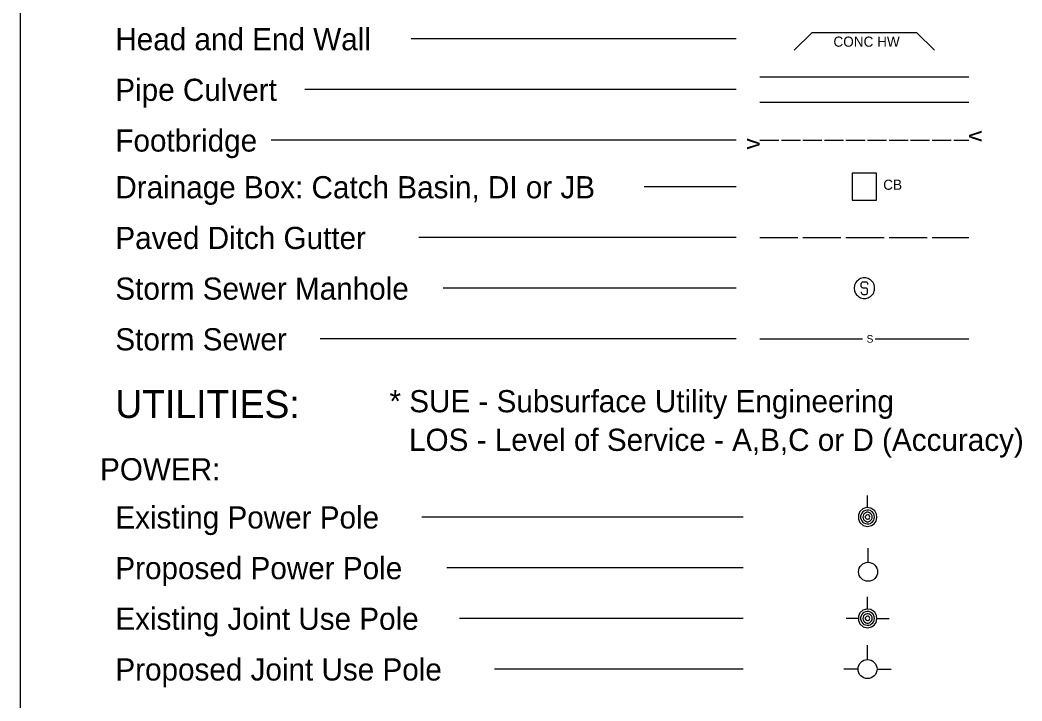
# Model space of a CAD drawing. Extents: x 811508 to 813252, y 647626 to 648754.
# Drawn here: x 812380 to 812789.1, y 648192.9 to 648471 of the extents above; entities that cross this region are included whole.
import ezdxf

# ---------------------------------------------------------------- set-up
doc = ezdxf.new("R2010")
doc.units = 0
doc.layers.add('Sheet_Symbology', color=7, linetype='Continuous')
doc.layers.add('z - Construction', color=7, linetype='Continuous')

msp = doc.modelspace()

# ---------------------------------------------------------------- linework, layer by layer
at = {"layer": 'Sheet_Symbology'}
for p, q in [((812672.47, 648463.4), (812539.68, 648463.4)), ((812696.12, 648458.66), (812703.44, 648465.99)), ((812703.44, 648465.99), (812746.13, 648465.99)), ((812746.13, 648465.99), (812753.46, 648458.66)), ((812682.1, 648447.87), (812767.48, 648447.87)), ((812672.47, 648442.7), (812496.33, 648442.7)), ((812682.1, 648437.53), (812767.48, 648437.53)), ((812672.47, 648422), (812482.58, 648422)), ((812682.1, 648422), (812689.86, 648422)), ((812690.89, 648422), (812698.66, 648422)), ((812699.69, 648422), (812707.45, 648422)), ((812708.49, 648422), (812716.25, 648422)), ((812717.28, 648422), (812725.05, 648422)), ((812726.08, 648422), (812733.84, 648422)), ((812734.88, 648422), (812742.64, 648422)), ((812743.68, 648422), (812751.44, 648422)), ((812752.47, 648422), (812760.24, 648422)), ((812761.27, 648422), (812767.48, 648422)), ((812672.47, 648402.92), (812634.91, 648402.92)), ((812672.47, 648382.22), (812542.91, 648382.22)), ((812682.1, 648382.22), (812697.62, 648382.22)), ((812699.69, 648382.22), (812715.22, 648382.22)), ((812717.28, 648382.22), (812732.81, 648382.22)), ((812734.88, 648382.22), (812750.4, 648382.22)), ((812752.47, 648382.22), (812767.48, 648382.22)), ((812672.47, 648361.52), (812552.75, 648361.52)), ((812723.54, 648362.26), (812723.54, 648363.37)), ((812724.28, 648364.11), (812725.39, 648364.11)), ((812725.39, 648361.55), (812724.28, 648361.55)), ((812726.1, 648363.37), (812726.1, 648363)), ((812726.1, 648359.7), (812726.1, 648360.85)), ((812723.54, 648360.07), (812723.54, 648359.7)), ((812724.28, 648359), (812725.39, 648359)), ((812672.47, 648340.82), (812502.53, 648340.82)), ((812682.1, 648340.82), (812724.04, 648340.82)), ((812729.21, 648340.82), (812767.48, 648340.82)), ((812726.08, 648271.88), (812726.08, 648276.85)), ((812675.36, 648268.06), (812544.05, 648268.06)), ((812726.3, 648249.55), (812726.3, 648255.37)), ((812675.36, 648247.36), (812554.28, 648247.36)), ((812726.08, 648230.48), (812726.08, 648235.45)), ((812675.36, 648226.66), (812559.53, 648226.66)), ((812722.26, 648226.66), (812717.3, 648226.66)), ((812729.9, 648226.66), (812734.87, 648226.66)), ((812726.08, 648209.86), (812726.08, 648215.68)), ((812675.36, 648205.96), (812573.7, 648205.96)), ((812722.2, 648205.98), (812716.38, 648205.98)), ((812729.96, 648205.98), (812735.78, 648205.98))]:
    msp.add_line(p, q, dxfattribs=at)
for points in [[(812719.81, 648397.42), (812729.76, 648397.42), (812729.76, 648408.43), (812719.81, 648408.43)], [(812726.08, 648264.24), (812727.69, 648264.55), (812728.76, 648265.31), (812729.6, 648266.38), (812729.9, 648267.83), (812729.75, 648269.21), (812728.99, 648270.58), (812727.46, 648271.73), (812725.7, 648271.88), (812724.17, 648271.42), (812722.95, 648270.35), (812722.34, 648268.9), (812722.34, 648267.22), (812722.95, 648265.77), (812724.32, 648264.62)], [(812726.08, 648222.84), (812727.69, 648223.15), (812728.76, 648223.91), (812729.6, 648224.98), (812729.9, 648226.43), (812729.75, 648227.81), (812728.99, 648229.18), (812727.46, 648230.33), (812725.7, 648230.48), (812724.17, 648230.02), (812722.95, 648228.95), (812722.34, 648227.5), (812722.34, 648225.82), (812722.95, 648224.37), (812724.32, 648223.22)]]:
    msp.add_lwpolyline(points, close=True, dxfattribs=at)
for points in [[(812724.79, 648365.72), (812724.25, 648365.69), (812723.75, 648365.59), (812723.24, 648365.42), (812722.77, 648365.18), (812722.33, 648364.92), (812721.93, 648364.58), (812721.56, 648364.18), (812721.26, 648363.77), (812720.99, 648363.3), (812720.82, 648362.8), (812720.69, 648362.29), (812720.62, 648361.79), (812720.62, 648361.25), (812720.69, 648360.75), (812720.82, 648360.21), (812720.99, 648359.74), (812721.26, 648359.27), (812721.56, 648358.86), (812721.93, 648358.46), (812722.33, 648358.13), (812722.77, 648357.86), (812723.24, 648357.62), (812723.75, 648357.45), (812724.28, 648357.35), (812724.79, 648357.32), (812725.33, 648357.35), (812725.83, 648357.45), (812726.34, 648357.62), (812726.81, 648357.86), (812727.24, 648358.13), (812727.65, 648358.46), (812728.02, 648358.86), (812728.32, 648359.27), (812728.59, 648359.74), (812728.76, 648360.24), (812728.89, 648360.75), (812728.96, 648361.25), (812728.96, 648361.79), (812728.89, 648362.29), (812728.76, 648362.83), (812728.59, 648363.3), (812728.32, 648363.77), (812728.02, 648364.18), (812727.65, 648364.58), (812727.24, 648364.92), (812726.81, 648365.18), (812726.34, 648365.42), (812725.83, 648365.59), (812725.29, 648365.69), (812724.79, 648365.72)], [(812723.54, 648363.37), (812723.61, 648363.61), (812723.71, 648363.81), (812723.85, 648363.94), (812724.05, 648364.04), (812724.28, 648364.11)], [(812724.28, 648361.55), (812724.05, 648361.59), (812723.85, 648361.69), (812723.71, 648361.86), (812723.61, 648362.06), (812723.54, 648362.26)], [(812725.39, 648364.11), (812725.6, 648364.04), (812725.8, 648363.94), (812725.97, 648363.81), (812726.07, 648363.61), (812726.1, 648363.37)], [(812726.1, 648360.81), (812726.07, 648361.05), (812725.97, 648361.25), (812725.8, 648361.42), (812725.6, 648361.52), (812725.39, 648361.55)], [(812723.54, 648359.74), (812723.61, 648359.5), (812723.71, 648359.3), (812723.85, 648359.13), (812724.05, 648359.03), (812724.28, 648359)], [(812725.39, 648359), (812725.6, 648359.03), (812725.8, 648359.13), (812725.97, 648359.3), (812726.07, 648359.5), (812726.1, 648359.74)], [(812728.91, 648268.06), (812728.83, 648268.75), (812728.6, 648269.36), (812728.22, 648269.89), (812727.76, 648270.35), (812727.23, 648270.66), (812726.54, 648270.81), (812725.93, 648270.89), (812725.24, 648270.74), (812724.63, 648270.51), (812724.17, 648270.12), (812723.72, 648269.59), (812723.41, 648269.05), (812723.25, 648268.37), (812723.25, 648267.76), (812723.41, 648267.07), (812723.72, 648266.53), (812724.17, 648266), (812724.63, 648265.62), (812725.24, 648265.39), (812725.93, 648265.23), (812726.54, 648265.31), (812727.23, 648265.46), (812727.76, 648265.77), (812728.22, 648266.23), (812728.6, 648266.76), (812728.83, 648267.37), (812728.91, 648268.06)], [(812727.99, 648268.06), (812727.92, 648268.6), (812727.69, 648269.13), (812727.3, 648269.51), (812726.85, 648269.82), (812726.39, 648269.97), (812725.78, 648269.97), (812725.32, 648269.82), (812724.86, 648269.51), (812724.48, 648269.13), (812724.25, 648268.6), (812724.17, 648268.06), (812724.25, 648267.53), (812724.48, 648266.99), (812724.86, 648266.61), (812725.32, 648266.3), (812725.78, 648266.15), (812726.39, 648266.15), (812726.85, 648266.3), (812727.3, 648266.61), (812727.69, 648266.99), (812727.92, 648267.53), (812727.99, 648268.06)], [(812727, 648268.06), (812726.92, 648268.44), (812726.69, 648268.75), (812726.39, 648268.9), (812726.01, 648268.98), (812725.62, 648268.83), (812725.32, 648268.6), (812725.17, 648268.21), (812725.17, 648267.91), (812725.32, 648267.53), (812725.62, 648267.3), (812726.01, 648267.14), (812726.39, 648267.22), (812726.69, 648267.37), (812726.92, 648267.68), (812727, 648268.06)], [(812728.91, 648226.66), (812728.83, 648227.35), (812728.6, 648227.96), (812728.22, 648228.5), (812727.76, 648228.95), (812727.23, 648229.26), (812726.54, 648229.41), (812725.93, 648229.49), (812725.24, 648229.34), (812724.63, 648229.11), (812724.17, 648228.73), (812723.72, 648228.19), (812723.41, 648227.65), (812723.25, 648226.97), (812723.25, 648226.36), (812723.41, 648225.67), (812723.72, 648225.13), (812724.17, 648224.6), (812724.63, 648224.22), (812725.24, 648223.99), (812725.93, 648223.83), (812726.54, 648223.91), (812727.23, 648224.06), (812727.76, 648224.37), (812728.22, 648224.83), (812728.6, 648225.36), (812728.83, 648225.97), (812728.91, 648226.66)], [(812727.99, 648226.66), (812727.92, 648227.2), (812727.69, 648227.73), (812727.3, 648228.11), (812726.85, 648228.42), (812726.39, 648228.57), (812725.78, 648228.57), (812725.32, 648228.42), (812724.86, 648228.11), (812724.48, 648227.73), (812724.25, 648227.2), (812724.17, 648226.66), (812724.25, 648226.13), (812724.48, 648225.59), (812724.86, 648225.21), (812725.32, 648224.9), (812725.78, 648224.75), (812726.39, 648224.75), (812726.85, 648224.9), (812727.3, 648225.21), (812727.69, 648225.59), (812727.92, 648226.13), (812727.99, 648226.66)], [(812727, 648226.66), (812726.92, 648227.04), (812726.69, 648227.35), (812726.39, 648227.5), (812726.01, 648227.58), (812725.62, 648227.43), (812725.32, 648227.2), (812725.17, 648226.82), (812725.17, 648226.51), (812725.32, 648226.13), (812725.62, 648225.9), (812726.01, 648225.75), (812726.39, 648225.82), (812726.69, 648225.97), (812726.92, 648226.28), (812727, 648226.66)]]:
    msp.add_lwpolyline(points, dxfattribs=at)
for centre in [(812726.3, 648245.67), (812726.08, 648205.96)]:
    msp.add_circle(centre, 3.88, dxfattribs=at)
at = {"layer": 'z - Construction'}
msp.add_line((812380.06, 648715.54), (812380.04, 647664.09), dxfattribs=at)

# ---------------------------------------------------------------- texts
at = {"layer": 'Sheet_Symbology'}
for s, height, p in [('Head and End Wall', 9.056, (812418.94, 648458.69)), ('Pipe Culvert', 9.056, (812418.94, 648438)), ('Footbridge', 9.056, (812418.96, 648417.3)), ('Drainage Box: Catch Basin, DI or JB', 9.056, (812418.96, 648398.22)), ('Paved Ditch Gutter', 9.056, (812418.96, 648377.51)), ('Storm Sewer Manhole', 9.056, (812418.96, 648356.81)), ('Storm Sewer', 9.056, (812418.96, 648336.11)), ('S', 3.1, (812725.69, 648339.27)), ('UTILITIES:', 11.385, (812418.94, 648308.5)), ('POWER:', 9.056, (812412.71, 648283.03)), ('Existing Power Pole', 9.056, (812418.96, 648263.36)), ('Proposed Power Pole', 9.056, (812418.96, 648242.67)), ('Existing Joint Use Pole', 9.056, (812418.96, 648221.98)), ('Proposed Joint Use Pole', 9.056, (812418.97, 648201.27))]:
    msp.add_text(s, height=height, dxfattribs=at).set_placement(p)
for s, height, rotation, p in [('CONC HW', 4.14, 360, (812712.16, 648460.13)), ('v', 6.83, 89.7591, (812682.08, 648418.13)), ('v', 6.83, 270.2409, (812767.47, 648425.87)), ('CB', 4.14, 360, (812732.49, 648401.7)), ('* SUE - Subsurface Utility Engineering', 9.056, 360, (812530.88, 648310.83)), ('LOS - Level of Service - A,B,C or D (Accuracy) ', 9.056, 360, (812538.87, 648295.06))]:
    msp.add_text(s, height=height, rotation=rotation, dxfattribs=at).set_placement(p)

doc.saveas('drawing.dxf')
